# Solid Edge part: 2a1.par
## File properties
Author: edge
Template: jis part.par
Last saved by: edge
Revision: 21
Application: Solid Edge
Accuracy: 0.990
文書内容のタイプ: 0
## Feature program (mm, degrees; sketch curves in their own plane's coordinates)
sketch for "unnamed Protrusion 1" plane through (0, 0, 0) normal (1, 0, 0) x-axis (0, 1, 0)
  line (0, 0) -> (-80, 0)
  line (-80, 0) -> (-80, 180)
  line (-80, 180) -> (0, 180)
  line (0, 180) -> (0, 0)
extrude "unnamed Protrusion 1" add finite 160 symmetric
thinwall "Thinwall_1"  Thickness = 20 mm
sketch for "unnamed Cutout 1" plane through (0, 0, 0) normal (0, -1, 0) x-axis (1, 0, 0)
  circle centre (0, 120) radius 27.5
extrude "unnamed Cutout 1" cut through
sketch for "unnamed Cutout 2" #1 plane through (0, 0, 0) normal (0, -1, 0) x-axis (1, 0, 0)
sketch for "unnamed Cutout 2" #2 plane through (0, 0, 0) normal (0, -1, 0) x-axis (1, 0, 0)
  circle centre (-50, 120) radius 6
extrude "unnamed Cutout 2" cut through along +normal
sketch for "unnamed Cutout 3" #1 plane through (0, 0, 0) normal (0, 0, 1) x-axis (1, 0, 0)
sketch for "unnamed Cutout 3" #2 plane through (0, 0, 0) normal (0, 0, 1) x-axis (1, 0, 0)
extrude "unnamed Cutout 3" cut through along +normal
chamfer "Chamfer_1" setback 5
chamfer "Chamfer_2" setback 5
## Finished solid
Body 1: solid body, 17 faces, 40 edges, 20 vertices.
  Faces by surface: plane 12, cylinder 5
  Edges by curve: line 30, circle 10
Bounding box of the edges (mm): 160.000 x 80.000 x 180.000, from (-80, -80, 0) to (80, 0, 180).
Cylindrical faces by radius (mm): R6 x2, R7.5 x2, R27.5 x1
Planar faces by outward normal: +x 1, +y 1, +z 2, -x 1, -y 2, -z 1, oblique 4
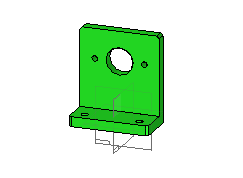
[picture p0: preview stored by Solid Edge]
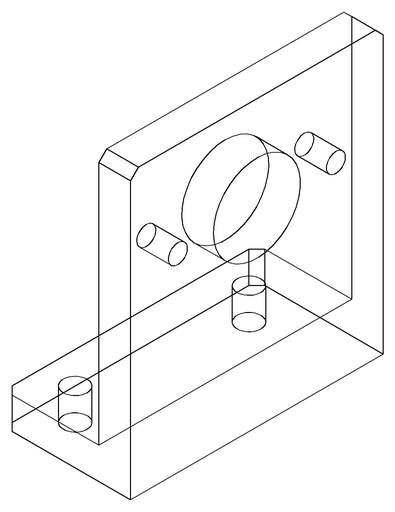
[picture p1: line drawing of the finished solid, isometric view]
